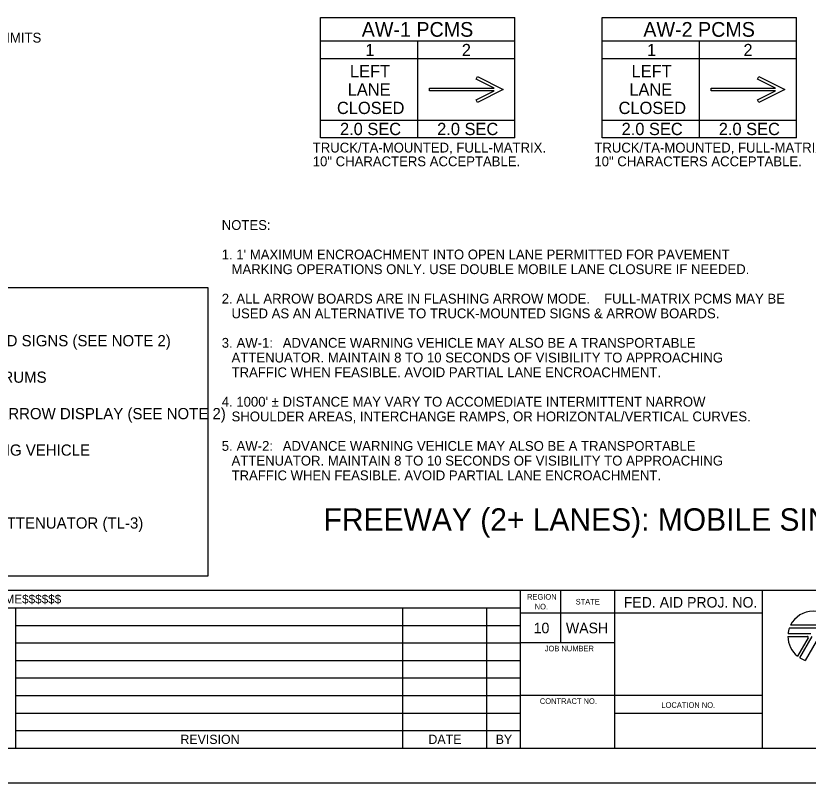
# Model space of a CAD drawing. Extents: x 0 to 17, y 0 to 11.
# Drawn here: x 2.92 to 8.57, y 0 to 5.47 of the extents above; entities that cross this region are included whole.
import ezdxf

# ---------------------------------------------------------------- set-up
doc = ezdxf.new("R2010")
doc.units = 0
for name, color, linetype in [('SH_GI_Logo_WSDOT', 7, 'Continuous'), ('SH_GI_PlotLimits', 7, 'Continuous'), ('SH_GI_SheetBorder1', 7, 'Continuous'), ('SH_GI_SheetBorder2', 7, 'Continuous'), ('SH_GI_SheetBorder3', 7, 'Continuous'), ('SH_GI_SheetTextInCells', 7, 'Continuous'), ('SH_GI_TitleBlockText', 7, 'Continuous'), ('TR_WZ_PortableChangeMessageSign', 7, 'Continuous'), ('TR_WZ_WorkZoneTextCurrent', 7, 'Continuous')]:
    doc.layers.add(name, color=color, linetype=linetype)

msp = doc.modelspace()

# ---------------------------------------------------------------- linework, layer by layer
at = {"layer": 'SH_GI_Logo_WSDOT'}
for p, q in [((8.4377, 1.1078), (8.6354, 1.1078)), ((8.6489, 1.1258), (8.4454, 1.1258)), ((8.4269, 1.0463), (8.5657, 1.0463)), ((8.59, 1.0643), (8.4278, 1.0643)), ((8.5709, 1.0373), (8.4948, 0.9054)), ((8.5121, 0.8933), (8.6004, 1.0463)), ((8.6541, 1.0553), (8.5502, 0.8754))]:
    msp.add_line(p, q, dxfattribs=at)
for centre, radius, start, end in [((8.6069, 1.0463), 0.18, 26.2103, 153.7897), ((8.6069, 1.0463), 0.18, 160.0216, 174.2608), ((8.6069, 1.0463), 0.18, 180, 231.4963), ((8.5657, 1.0403), 0.006, 330, 90), ((8.6069, 1.0463), 0.18, 238.2117, 251.6613)]:
    msp.add_arc(centre, radius, start, end, dxfattribs=at)
at = {"layer": 'SH_GI_PlotLimits'}
msp.add_lwpolyline([(0, 11), (17, 11), (17, 0), (0, 0)], close=True, dxfattribs=at)
at = {"layer": 'SH_GI_SheetBorder1'}
for p, q in [((8.245, 1.2125), (6.52, 1.2125)), ((2.92, 1.125), (6.52, 1.125)), ((2.92, 1), (6.52, 1)), ((2.92, 0.875), (6.52, 0.875)), ((2.92, 0.75), (6.52, 0.75)), ((2.92, 0.625), (6.52, 0.625)), ((2.92, 0.5), (6.52, 0.5)), ((7.1913, 0.5), (8.245, 0.5))]:
    msp.add_line(p, q, dxfattribs=at)
at = {"layer": 'SH_GI_SheetBorder2'}
for p, q in [((6.8073, 1), (6.8073, 1.375)), ((7.1913, 1), (6.52, 1)), ((8.245, 0.625), (6.52, 0.625)), ((2.92, 0.375), (6.52, 0.375))]:
    msp.add_line(p, q, dxfattribs=at)
at = {"layer": 'SH_GI_SheetBorder3'}
for p, q in [((1, 1.375), (16.75, 1.375)), ((6.52, 0.25), (6.52, 1.375)), ((7.1913, 0.25), (7.1913, 1.375)), ((8.245, 0.25), (8.245, 1.375)), ((1, 1.25), (6.52, 1.25)), ((2.92, 0.25), (2.92, 1.25)), ((5.68, 0.25), (5.68, 1.25)), ((6.28, 0.25), (6.28, 1.25)), ((1, 0.25), (16.75, 0.25))]:
    msp.add_line(p, q, dxfattribs=at)
at = {"layer": 'TR_WZ_PortableChangeMessageSign'}
for p, q in [((5.0937, 5.4586), (6.4797, 5.4586)), ((5.0937, 4.6018), (5.0937, 5.4586)), ((6.4797, 4.6018), (6.4797, 5.4586)), ((7.1024, 5.4586), (8.4884, 5.4586)), ((7.1024, 4.6018), (7.1024, 5.4586)), ((8.4884, 4.6018), (8.4884, 5.4586)), ((6.4797, 5.2906), (5.0937, 5.2906)), ((5.7867, 4.6018), (5.7867, 5.2906)), ((8.4884, 5.2906), (7.1024, 5.2906)), ((7.7954, 4.6018), (7.7954, 5.2906)), ((5.7867, 5.1646), (5.0937, 5.1646)), ((6.4797, 5.1646), (5.7867, 5.1646)), ((7.7954, 5.1646), (7.1024, 5.1646)), ((8.4884, 5.1646), (7.7954, 5.1646)), ((6.2117, 5.0395), (6.3957, 4.9462)), ((8.2204, 5.0395), (8.4044, 4.9462)), ((5.8707, 4.9357), (5.8707, 4.9567)), ((5.8707, 4.9567), (6.3305, 4.9567)), ((6.3305, 4.9357), (5.8707, 4.9357)), ((7.8794, 4.9357), (7.8794, 4.9567)), ((7.8794, 4.9567), (8.3392, 4.9567)), ((8.3392, 4.9357), (7.8794, 4.9357)), ((5.0937, 4.7278), (5.7867, 4.7278)), ((5.7867, 4.7278), (6.4797, 4.7278)), ((7.1024, 4.7278), (7.7954, 4.7278)), ((7.7954, 4.7278), (8.4884, 4.7278)), ((6.4797, 4.6018), (5.0937, 4.6018)), ((8.4884, 4.6018), (7.1024, 4.6018))]:
    msp.add_line(p, q, dxfattribs=at)
for points in [[(6.3305, 4.9567), (6.2023, 5.0208), (6.207, 5.0302), (6.2117, 5.0395)], [(8.3392, 4.9567), (8.211, 5.0208), (8.2157, 5.0302), (8.2204, 5.0395)], [(6.3957, 4.9462), (6.2117, 4.8528), (6.207, 4.8622), (6.2023, 4.8715), (6.3305, 4.9357)], [(8.4044, 4.9462), (8.2204, 4.8528), (8.2157, 4.8622), (8.211, 4.8715), (8.3392, 4.9357)]]:
    msp.add_lwpolyline(points, dxfattribs=at)
at = {"layer": 'TR_WZ_WorkZoneTextCurrent'}
msp.add_lwpolyline([(1.1, 3.535), (4.2886, 3.535), (4.2886, 1.475), (1.1, 1.475)], close=True, dxfattribs=at)

# ---------------------------------------------------------------- texts
at = {"layer": 'SH_GI_SheetTextInCells'}
for s, height, p in [('REGION', 0.04, (6.5662, 1.3088)), ('STATE', 0.04, (6.9129, 1.2738)), ('FED. AID PROJ. NO.', 0.075, (7.2558, 1.252)), ('NO.', 0.04, (6.6206, 1.2387)), ('10', 0.075, (6.6136, 1.0688)), ('WASH', 0.075, (6.8434, 1.0688)), ('JOB NUMBER', 0.04, (6.6925, 0.94)), ('CONTRACT NO.', 0.04, (6.6574, 0.565)), ('LOCATION NO.', 0.04, (7.5244, 0.537)), ('REVISION', 0.066, (4.0938, 0.2795)), ('DATE', 0.066, (5.8627, 0.2795)), ('BY', 0.066, (6.3424, 0.2795))]:
    msp.add_text(s, height=height, dxfattribs=at).set_placement(p)
at = {"layer": 'SH_GI_TitleBlockText'}
msp.add_text('$$$$$$$$DESIGNFILENAME$$$$$$', height=0.0625, dxfattribs=at).set_placement((1.8545, 1.2812))
at = {"layer": 'TR_WZ_PortableChangeMessageSign'}
for s, height, p in [('AW-1 PCMS', 0.105, (5.3869, 5.3221)), ('AW-2 PCMS', 0.105, (7.3956, 5.3221)), ('MOBILE LANE CLOSURE OPERATION LIMITS ', 0.07, (1.0938, 5.2809)), ('1', 0.0875, (5.4128, 5.1838)), ('2', 0.0875, (6.1008, 5.1838)), ('1', 0.0875, (7.4215, 5.1838)), ('2', 0.0875, (8.1094, 5.1838)), ('LEFT', 0.0875, (5.303, 5.0337)), ('LEFT', 0.0875, (7.3116, 5.0337)), ('LANE', 0.0875, (5.2869, 4.9024)), ('LANE', 0.0875, (7.2956, 4.9024)), ('CLOSED', 0.0875, (5.2104, 4.7712)), ('CLOSED', 0.0875, (7.2191, 4.7712)), ('2.0 SEC', 0.0875, (5.232, 4.621)), ('2.0 SEC', 0.0875, (5.925, 4.621)), ('2.0 SEC', 0.0875, (7.2407, 4.621)), ('2.0 SEC', 0.0875, (7.9337, 4.621)), ('TRUCK/TA-MOUNTED, FULL-MATRIX.', 0.07, (5.0377, 4.4968)), ('TRUCK/TA-MOUNTED, FULL-MATRIX.', 0.07, (7.0464, 4.4968)), ('10" CHARACTERS ACCEPTABLE.', 0.07, (5.0377, 4.3988)), ('10" CHARACTERS ACCEPTABLE.', 0.07, (7.0464, 4.3988))]:
    msp.add_text(s, height=height, rotation=360, dxfattribs=at).set_placement(p)
at = {"layer": 'TR_WZ_WorkZoneTextCurrent'}
for s, height, p in [('NOTES:', 0.07, (4.3886, 3.9447)), ("1. 1' MAXIMUM ENCROACHMENT INTO OPEN LANE PERMITTED FOR PAVEMENT ", 0.07, (4.3886, 3.7347)), ('MARKING OPERATIONS ONLY. USE DOUBLE MOBILE LANE CLOSURE IF NEEDED.', 0.07, (4.4586, 3.6297)), ('2. ALL ARROW BOARDS ARE IN FLASHING ARROW MODE. ', 0.07, (4.3886, 3.4197)), ('FULL-MATRIX PCMS MAY BE ', 0.07, (7.1158, 3.4197)), ('USED AS AN ALTERNATIVE TO TRUCK-MOUNTED SIGNS & ARROW BOARDS.', 0.07, (4.4586, 3.3147)), ('TRUCK/TA-MOUNTED SIGNS (SEE NOTE 2)', 0.08, (1.82, 3.115)), ('3. ', 0.07, (4.3886, 3.1047)), ('AW-1:', 0.07, (4.4943, 3.1047)), (' ADVANCE WARNING VEHICLE MAY ALSO BE A TRANSPORTABLE ', 0.07, (4.7978, 3.1047)), ('ATTENUATOR. MAINTAIN 8 TO 10 SECONDS OF VISIBILITY TO APPROACHING ', 0.07, (4.4586, 2.9997)), ('TRAFFIC WHEN FEASIBLE. AVOID PARTIAL LANE ENCROACHMENT.', 0.07, (4.4586, 2.8947)), ('TRAFFIC SAFETY DRUMS', 0.08, (1.82, 2.855)), ("4. 1000' ± DISTANCE MAY VARY TO ACCOMEDIATE INTERMITTENT NARROW ", 0.07, (4.3886, 2.6847)), ('TRUCK-MOUNTED ARROW DISPLAY (SEE NOTE 2)', 0.08, (1.82, 2.595)), ('SHOULDER AREAS, INTERCHANGE RAMPS, OR HORIZONTAL/VERTICAL CURVES.', 0.07, (4.4586, 2.5797)), ('5. ', 0.07, (4.3886, 2.3697)), ('AW-2:', 0.07, (4.4943, 2.3697)), (' ADVANCE WARNING VEHICLE MAY ALSO BE A TRANSPORTABLE ', 0.07, (4.7978, 2.3697)), ('ADVANCED WARNING VEHICLE', 0.08, (1.82, 2.335)), ('ATTENUATOR. MAINTAIN 8 TO 10 SECONDS OF VISIBILITY TO APPROACHING ', 0.07, (4.4586, 2.2647)), ('TRAFFIC WHEN FEASIBLE. AVOID PARTIAL LANE ENCROACHMENT.', 0.07, (4.4586, 2.1597)), ('FREEWAY (2+ LANES): MOBILE SINGLE RIGHT LANE CLOSURE FOR PAVEMENT MARKING OPERATIONS', 0.16, (5.1148, 1.7997)), ('TRANSPORTABLE ATTENUATOR (TL-3)', 0.08, (1.82, 1.815))]:
    msp.add_text(s, height=height, rotation=360, dxfattribs=at).set_placement(p)

doc.saveas('drawing.dxf')
